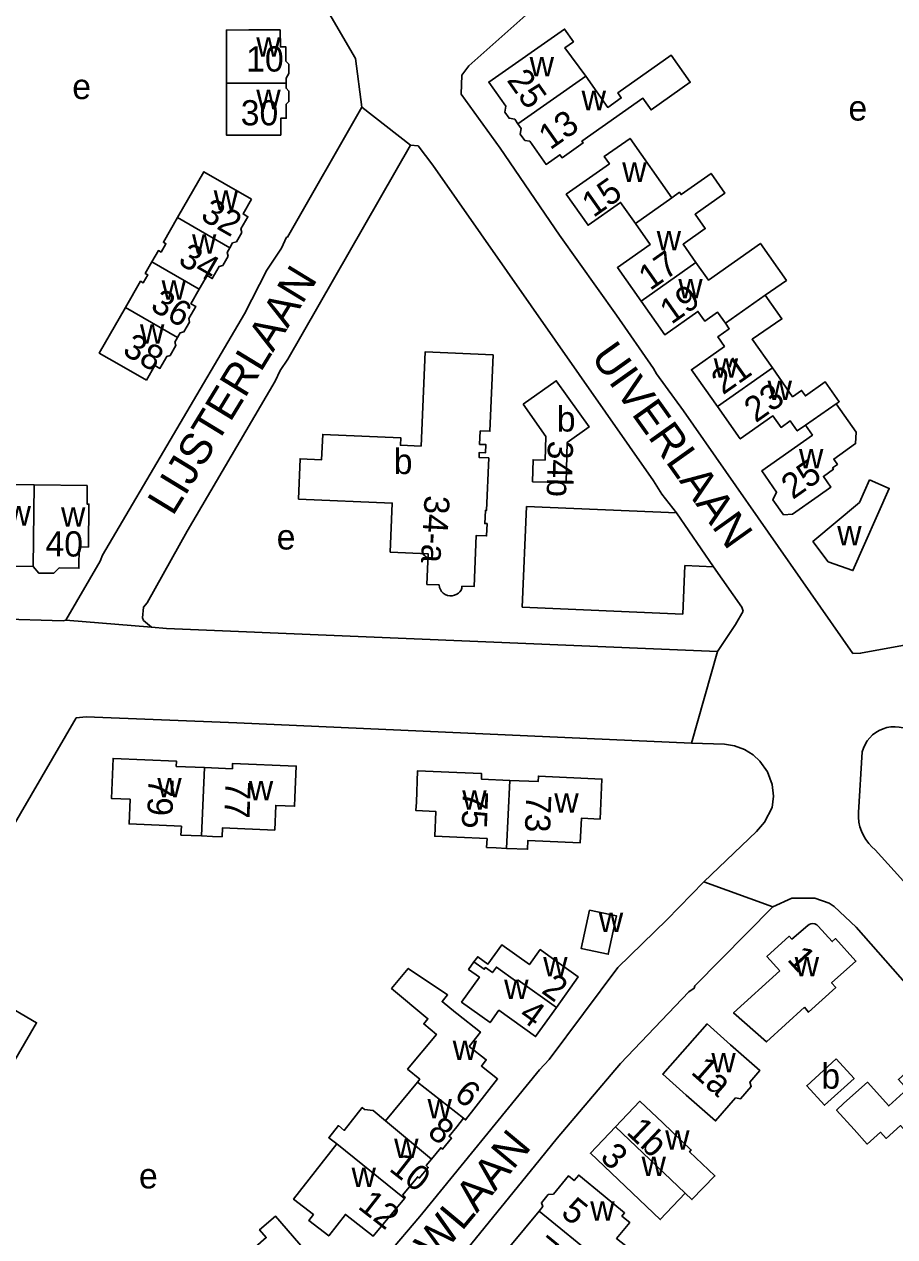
# Model space of a CAD drawing. Extents: x 161775 to 163181, y 382878 to 383925.
# Drawn here: x 162431.4 to 162569.5, y 383562.8 to 383755.2 of the extents above; entities that cross this region are included whole.
import ezdxf

# ---------------------------------------------------------------- set-up
doc = ezdxf.new("R2010")
doc.units = 0
for name, color, linetype in [('BLT_Basislijn', 7, 'Continuous'), ('BLT_Bebouwing', 7, 'Continuous'), ('BLT_Centroide', 7, 'Continuous'), ('BLT_Huisnummer', 7, 'Continuous'), ('BLT_Huisnummer_ tussenligend', 7, 'Continuous'), ('BLT_Huisnummer_reeks', 7, 'Continuous'), ('BLT_Onderverdeling_panden', 7, 'Continuous'), ('BLT_Straatnaam', 7, 'Continuous'), ('BLT_Vlakafsluiter', 7, 'Continuous')]:
    doc.layers.add(name, color=color, linetype=linetype)

msp = doc.modelspace()

# ---------------------------------------------------------------- linework, layer by layer
at = {"layer": 'BLT_Basislijn'}
for p, q in [((162471.79, 383770.6), (162483.91, 383749.78)), ((162483.91, 383749.78), (162484.96, 383742.04)), ((162484.96, 383742.04), (162473.14, 383721.44)), ((162473.19, 383702.07), (162492.67, 383736)), ((162492.67, 383736), (162493.88, 383735.92)), ((162493.88, 383735.92), (162496.2, 383732.84)), ((162496.2, 383732.84), (162531.21, 383682.78)), ((162472.98, 383721.44), (162472.2, 383719.67)), ((162473.14, 383721.44), (162472.98, 383721.44)), ((162472.2, 383719.67), (162469.88, 383716.2)), ((162469.88, 383716.2), (162466.31, 383709.26)), ((162466.31, 383709.26), (162443.82, 383670.95)), ((162471.98, 383700.26), (162473.19, 383702.07)), ((162471.18, 383698.57), (162471.98, 383700.26)), ((162457.22, 383674.75), (162471.18, 383698.57)), ((162531.21, 383682.78), (162532.49, 383680.64)), ((162532.49, 383680.64), (162534.85, 383677.66)), ((162511.07, 383678.7), (162510.38, 383662.73)), ((162511.07, 383678.7), (162534.85, 383677.66)), ((162534.85, 383677.66), (162540.71, 383669.12)), ((162450.87, 383663.42), (162457.22, 383674.75)), ((162443.82, 383670.95), (162443.46, 383670.03)), ((162443.46, 383670.03), (162437.98, 383660.67)), ((162535.85, 383661.62), (162536.19, 383669.32)), ((162540.71, 383669.12), (162536.19, 383669.32)), ((162540.71, 383669.12), (162545.19, 383662.72)), ((162450.3, 383662.72), (162450.87, 383663.42)), ((162450.17, 383661.04), (162450.3, 383662.72)), ((162510.38, 383662.73), (162535.85, 383661.62)), ((162545.41, 383662.09), (162544.22, 383659.95)), ((162545.19, 383662.72), (162545.41, 383662.09)), ((162437.59, 383660.52), (162425, 383660.96)), ((162437.98, 383660.67), (162437.59, 383660.52)), ((162450.33, 383660.62), (162450.17, 383661.04)), ((162451.57, 383659.53), (162450.33, 383660.62)), ((162453.94, 383659.34), (162451.57, 383659.53)), ((162541.37, 383655.69), (162453.94, 383659.34)), ((162544.22, 383659.95), (162541.37, 383655.69)), ((162412.37, 383598.34), (162439.64, 383645.18)), ((162439.64, 383645.18), (162441.21, 383645.29)), ((162441.21, 383645.29), (162465.12, 383644.39)), ((162465.12, 383644.39), (162537.22, 383641.15)), ((162537.22, 383641.15), (162542.43, 383640.97)), ((162564.3, 383639.76), (162563.69, 383630.15)), ((162548.8, 383628.62), (162547.54, 383627.14)), ((162547.54, 383627.14), (162539.2, 383619.13)), ((162566.35, 383624.21), (162577.05, 383612.32)), ((162539.2, 383619.13), (162533.33, 383613.11)), ((162533.33, 383613.11), (162525.53, 383605.54)), ((162525.53, 383605.54), (162514.66, 383590.97)), ((162514.66, 383590.97), (162513.14, 383589.33)), ((162513.14, 383589.33), (162494.16, 383566.07)), ((162494.16, 383566.07), (162488.99, 383560.01))]:
    msp.add_line(p, q, dxfattribs=at)
for points in [[(162581.31, 383759.17), (162559.03, 383792.81), (162557.89, 383792.62), (162542.81, 383782.75), (162531.95, 383775.94), (162528.54, 383772.6), (162528.54, 383772.35), (162501.9, 383748.57), (162500.78, 383747.14), (162500.69, 383744.11), (162506.86, 383735.52), (162516.26, 383721.74), (162525.33, 383709.05), (162531.21, 383700.6), (162531.65, 383699.73), (162535.97, 383693.84), (162562.82, 383655.34), (162564.03, 383655.39), (162577.08, 383657.78)], [(162570.77, 383643.55), (162570.14, 383643.68), (162569.5, 383643.74), (162568.86, 383643.71), (162568.22, 383643.61), (162567.6, 383643.43), (162567.01, 383643.17), (162566.45, 383642.85), (162565.94, 383642.45), (162565.48, 383642), (162565.08, 383641.49), (162564.75, 383640.94), (162564.48, 383640.35), (162564.3, 383639.76)], [(162542.43, 383640.97), (162544.05, 383640.71), (162545.65, 383640.13), (162547, 383639.28), (162548.07, 383638.26), (162549.3, 383636.58), (162550.01, 383634.57), (162550.21, 383632.74), (162549.99, 383630.95), (162548.8, 383628.62)], [(162563.69, 383630.15), (162563.69, 383629.39), (162563.78, 383628.63), (162563.94, 383627.89), (162564.18, 383627.18), (162564.49, 383626.49), (162564.87, 383625.83), (162565.33, 383625.22), (162565.84, 383624.67), (162566.35, 383624.21)], [(162550.13, 383615.17), (162537.75, 383602.64), (162537.62, 383602.25), (162536.8, 383601.68), (162525.96, 383590.3), (162515.92, 383578.47), (162512.31, 383574.02)], [(162571.49, 383602.7), (162563.33, 383611.96), (162559.83, 383615.2), (162559.03, 383615.74), (162556.77, 383616.56), (162553.14, 383616.56), (162550.13, 383615.17)], [(162512.31, 383574.02), (162490.5, 383547.14), (162490.5, 383546.29), (162493.91, 383542.53), (162494, 383541.83), (162480.94, 383530.56)]]:
    msp.add_lwpolyline(points, dxfattribs=at)
at = {"layer": 'BLT_Bebouwing'}
for p, q in [((162424.35, 383682.19), (162432.96, 383682.11)), ((162432.96, 383682.11), (162441.4, 383682.02)), ((162432.83, 383669.15), (162424.22, 383669.24)), ((162513.05, 383566.89), (162508.42, 383561.3))]:
    msp.add_line(p, q, dxfattribs=at)
for points in [[(162463.46, 383745.85), (162463.47, 383750), (162463.46, 383754.28), (162467.01, 383754.29), (162472.01, 383754.31)], [(162472.01, 383754.31), (162472.02, 383751.6), (162472.9, 383751.61), (162472.9, 383750), (162472.9, 383749.31), (162473.36, 383748.85), (162473.36, 383747.38), (162472.93, 383746.64), (162472.93, 383745.84)], [(162520.44, 383746.96), (162517.12, 383751.43), (162518.5, 383752.41), (162517.09, 383754.43), (162505.06, 383746.02), (162507.77, 383742.18), (162507.61, 383741.27), (162508.3, 383740.28), (162509.18, 383740.13), (162509.7, 383739.39)], [(162509.7, 383739.39), (162510.22, 383738.65), (162510.07, 383737.78), (162510.79, 383736.76), (162511.58, 383736.63), (162514.16, 383732.96), (162516.36, 383734.5), (162516.7, 383734.02), (162520.03, 383736.37), (162519.85, 383736.64), (162529.51, 383743.46), (162530.82, 383741.61), (162537.03, 383745.99), (162534, 383750.28), (162525.52, 383744.3), (162526.08, 383743.5), (162523.94, 383741.99), (162520.44, 383746.96)], [(162463.46, 383745.85), (162463.46, 383737.6), (162467.07, 383737.59), (162472.07, 383737.59)], [(162472.07, 383737.59), (162472.07, 383740.29), (162472.94, 383740.29), (162472.94, 383742.49), (162473.37, 383742.92), (162473.37, 383744.6), (162472.93, 383745.04), (162472.93, 383745.84)], [(162534.11, 383727.67), (162527.47, 383737.09), (162523.39, 383734.22), (162524.21, 383733.06), (162517.36, 383728.23), (162520.83, 383723.3), (162525.97, 383726.93), (162528.32, 383723.6)], [(162467.46, 383727.44), (162463.12, 383729.93), (162459.89, 383731.79), (162455.7, 383724.51)], [(162534.11, 383727.67), (162535.31, 383728.53), (162535.57, 383728.17), (162540.33, 383731.52), (162542.53, 383728.4), (162537.79, 383725.05), (162539.39, 383722.78), (162535.88, 383720.3), (162537.93, 383717.39)], [(162464.01, 383719.73), (162464.45, 383720.49), (162465.05, 383720.65), (162465.91, 383722.14), (162465.75, 383722.72), (162466.88, 383724.66), (162466.11, 383725.1), (162467.46, 383727.44)], [(162455.7, 383724.51), (162453.46, 383720.61), (162453.87, 383720.37), (162453.1, 383719.04), (162452.67, 383719.29), (162451.62, 383717.48)], [(162528.32, 383723.6), (162530.67, 383720.26), (162525.47, 383716.59), (162529.23, 383711.26)], [(162459.16, 383713.15), (162460.4, 383715.31), (162461.2, 383714.85), (162462.29, 383716.74), (162462.88, 383716.9), (162463.73, 383718.39), (162463.58, 383718.97), (162464.01, 383719.73)], [(162548.91, 383712.19), (162552.28, 383714.56), (162548.15, 383720.42), (162539.9, 383714.6), (162537.93, 383717.39)], [(162451.62, 383717.48), (162450.58, 383715.67), (162450.99, 383715.44), (162450.26, 383714.17), (162449.84, 383714.41), (162447.45, 383710.26)], [(162455.72, 383705.5), (162456.14, 383706.23), (162456.73, 383706.39), (162457.63, 383707.95), (162457.48, 383708.49), (162458.6, 383710.43), (162457.84, 383710.86), (162459.16, 383713.15)], [(162529.23, 383711.26), (162532.99, 383705.92), (162538.25, 383709.63), (162539.34, 383708.08), (162541.36, 383709.51), (162542.6, 383707.75)], [(162550.05, 383700.66), (162546.83, 383705.21), (162551.55, 383708.44), (162548.91, 383712.19)], [(162450.78, 383698.71), (162446.44, 383701.21), (162443.29, 383703.03), (162447.45, 383710.26)], [(162542.6, 383707.75), (162543.2, 383706.89), (162541.38, 383705.6), (162542.45, 383704.07), (162537.22, 383700.39), (162541.35, 383694.53)], [(162455.72, 383705.5), (162455.3, 383704.77), (162455.45, 383704.23), (162454.52, 383702.63), (162453.99, 383702.48), (162452.9, 383700.59), (162452.12, 383701.04), (162450.78, 383698.71)], [(162489.43, 383671.42), (162489.77, 383679.23), (162474.91, 383679.87), (162475.13, 383686.26), (162478.56, 383686.11), (162478.73, 383690.12), (162491.1, 383689.59), (162491.05, 383688.41), (162494.33, 383688.26), (162494.97, 383703.22), (162505.77, 383702.75)], [(162505.77, 383702.75), (162505.24, 383690.61), (162503.71, 383690.68), (162503.62, 383688.54), (162504.62, 383688.5), (162504.57, 383687.22), (162503.57, 383687.26), (162503.53, 383686.48), (162505.07, 383686.42)], [(162560.18, 383694.97), (162560.65, 383695.3), (162558.43, 383698.46), (162555.28, 383696.24), (162554.67, 383697.1), (162553.26, 383696.1), (162550.05, 383700.66)], [(162510.51, 383694.91), (162514.13, 383689.81), (162514, 383686.06), (162512.1, 383686.1), (162512.01, 383682.61), (162517.35, 383682.55), (162517.52, 383688.85), (162520.97, 383691.31), (162515.77, 383698.64), (162510.51, 383694.91)], [(162541.35, 383694.53), (162544.96, 383689.41), (162550.13, 383693.06), (162551.42, 383691.23), (162552.88, 383692.26), (162554, 383690.67), (162555.3, 383691.57)], [(162560.18, 383694.97), (162563.35, 383690.48), (162563.25, 383688.66), (162559.77, 383686.2), (162560.37, 383685.35), (162559.59, 383684.8), (162559.74, 383684.6), (162558.14, 383683.46), (162559.33, 383681.77), (162557.31, 383680.35), (162553.22, 383677.47), (162551.82, 383677.34), (162550.14, 383679.73), (162550.72, 383680.98), (162548.35, 383684.34), (162556.4, 383690.01), (162555.3, 383691.57)], [(162500.82, 383666.06), (162502.74, 383665.98), (162503.09, 383674.09), (162504.71, 383674.02), (162504.79, 383675.97), (162504.44, 383675.98), (162504.53, 383678.06), (162504.7, 383678.05), (162505.07, 383686.42)], [(162441.4, 383682.02), (162441.37, 383679.08), (162441.65, 383679.08), (162441.58, 383672.25), (162440.1, 383672.26), (162440.07, 383668.9), (162436.94, 383668.93), (162436.09, 383668.1)], [(162489.43, 383671.42), (162495.46, 383671.16), (162495.25, 383666.32), (162497.2, 383666.24)], [(162436.09, 383668.1), (162433.7, 383668.12), (162432.83, 383669.15)], [(162497.2, 383666.24), (162497.25, 383665.86), (162497.39, 383665.5), (162497.59, 383665.18), (162497.86, 383664.91), (162498.17, 383664.7), (162498.53, 383664.56), (162498.9, 383664.49), (162499.28, 383664.51), (162499.65, 383664.61), (162499.99, 383664.78), (162500, 383664.78)], [(162500.82, 383666.06), (162500.78, 383665.74), (162500.67, 383665.43), (162500.49, 383665.15), (162500.25, 383664.93), (162500, 383664.78)], [(162459.96, 383637.26), (162455.51, 383637.45), (162455.54, 383638.29), (162445.49, 383638.71), (162445.23, 383632.36), (162448.19, 383632.23), (162448.02, 383628.32), (162456.31, 383627.97), (162456.25, 383626.56), (162459.5, 383626.43)], [(162459.5, 383626.43), (162461.24, 383626.35), (162462.76, 383626.29), (162462.82, 383627.69), (162471.12, 383627.34), (162471.28, 383631.26), (162474.26, 383631.14), (162474.32, 383632.5), (162474.53, 383637.49), (162464.44, 383637.92), (162464.4, 383637.08), (162459.96, 383637.26)], [(162507.9, 383624.45), (162506.23, 383624.52), (162504.72, 383624.59), (162504.79, 383626), (162500, 383626.22), (162496.5, 383626.38), (162496.68, 383630.28), (162493.52, 383630.43), (162493.58, 383631.76), (162493.79, 383636.75), (162500, 383636.49), (162503.93, 383636.3), (162503.89, 383635.45), (162508.39, 383635.24)], [(162508.39, 383635.24), (162512.9, 383635.04), (162512.94, 383635.91), (162523, 383635.45), (162522.71, 383629.1), (162519.76, 383629.23), (162519.58, 383625.33), (162511.29, 383625.7), (162511.23, 383624.3), (162507.9, 383624.45)], [(162521.02, 383614.66), (162525.31, 383613.76), (162524.02, 383607.66), (162519.73, 383608.56), (162521.02, 383614.66)], [(162551.24, 383605.04), (162549.19, 383607.29), (162552.73, 383610.51), (162553.15, 383610.05), (162555.65, 383612.23)], [(162557.33, 383612.13), (162559.54, 383609.65), (162560.07, 383610.13), (162563.29, 383606.57), (162559.43, 383603.09), (162560.1, 383602.35), (162555.8, 383598.46), (162555.12, 383599.23)], [(162557.33, 383612.13), (162557.09, 383612.33), (162556.8, 383612.45), (162556.48, 383612.51), (162556.17, 383612.48), (162555.87, 383612.37), (162555.65, 383612.23)], [(162502.72, 383606.44), (162503.31, 383607.25), (162504.94, 383606.08), (162507.13, 383609.14), (162511.51, 383606.01), (162513.22, 383608.39), (162515.2, 383606.97), (162519.27, 383604.06), (162515.79, 383599.2)], [(162493.75, 383587.36), (162494.13, 383587.83), (162492.2, 383589.43), (162496.76, 383594.93), (162494.75, 383596.61), (162495.43, 383597.43), (162489.66, 383602.22), (162492.31, 383605.41), (162498.54, 383601.19), (162497.67, 383600.13), (162499.8, 383598.42), (162500, 383598.25), (162503.74, 383595.3), (162501.96, 383593.04), (162504.66, 383590.9), (162503.89, 383589.92), (162506.47, 383587.87), (162501.4, 383581.38), (162501.06, 383581.65)], [(162502.72, 383606.44), (162501.86, 383605.24), (162503.59, 383604.01), (162500.75, 383600.05), (162505.27, 383596.8), (162506.68, 383598.77), (162512.49, 383594.6), (162515.79, 383599.2)], [(162551.24, 383605.04), (162543.9, 383598.34), (162549.09, 383593.75), (162555.12, 383599.23)], [(162419.03, 383596.27), (162419.5, 383597.09), (162419.23, 383598.12), (162420.01, 383599.47), (162421.01, 383599.74), (162421.52, 383600.63), (162421.91, 383600.4), (162423.19, 383602.63), (162427.52, 383600.13), (162433.34, 383596.78), (162429.54, 383590.2), (162428.32, 383590.91)], [(162543.43, 383593.28), (162548.08, 383589.19), (162546.47, 383587.38), (162546.71, 383586.67), (162544.97, 383584.7), (162544.22, 383584.85), (162541.03, 383581.22), (162536.4, 383585.3), (162532.65, 383588.6), (162539.68, 383596.59), (162543.43, 383593.28)], [(162572.93, 383577.64), (162578.49, 383582.65), (162582.2, 383586), (162577.17, 383591.58), (162575.84, 383590.38), (162574.54, 383591.83), (162570.04, 383587.78), (162571.43, 383586.25), (162568.5, 383583.6), (162565.12, 383587.35), (162561.4, 383584), (162560.22, 383582.94), (162563.02, 383579.83), (162565.09, 383577.54), (162567.17, 383579.42), (162568.08, 383578.42), (162570.37, 383580.48), (162572.93, 383577.64)], [(162488.67, 383581.24), (162493.75, 383587.36)], [(162536.24, 383569.73), (162537.3, 383568.72), (162540.94, 383572.49), (162536.91, 383576.32), (162537.18, 383576.6), (162537.18, 383576.59), (162532.65, 383580.9), (162529.02, 383584.34), (162525.15, 383580.27)], [(162488.67, 383581.24), (162486.75, 383582.84), (162485.38, 383583), (162484.99, 383583.32), (162482.14, 383579.71), (162481.22, 383580.48), (162479.69, 383578.55), (162480.98, 383577.55)], [(162496.01, 383575.15), (162497.44, 383576.95), (162497.72, 383576.71), (162499.16, 383578.45), (162498.77, 383578.77), (162500, 383580.25), (162501.06, 383581.65)], [(162525.15, 383580.27), (162521.18, 383576.09), (162532.27, 383565.56), (162536.24, 383569.73)], [(162480.98, 383577.55), (162474.12, 383568.78), (162477.25, 383566.35), (162476.52, 383565.42), (162479.68, 383562.96), (162482.33, 383566.37), (162486.74, 383562.94), (162491.69, 383568.92)], [(162496.01, 383575.15), (162495.15, 383574.11), (162495.26, 383574.02)], [(162495.26, 383574.02), (162495.47, 383573.84), (162494.05, 383572.13), (162493.8, 383572.34), (162491.4, 383569.44)], [(162522.51, 383559.16), (162523.98, 383557.96), (162526.8, 383561.37), (162525.34, 383562.58), (162527.42, 383565.08), (162526.19, 383566.1), (162526.61, 383566.6), (162523.2, 383569.43), (162519.35, 383572.62), (162518.61, 383571.73), (162517.71, 383572.47), (162515.33, 383569.6), (162514.49, 383569.52), (162513.42, 383568.23), (162513.65, 383567.61), (162513.05, 383566.89)], [(162491.4, 383569.44), (162491.83, 383569.09), (162491.69, 383568.92)], [(162466.69, 383560.04), (162469.79, 383562.7), (162468.72, 383563.93), (162471.24, 383566.11), (162476.95, 383559.49), (162480.21, 383555.7), (162477.43, 383553.3), (162477.74, 383552.93), (162475.28, 383550.82), (162474.95, 383551.2), (162474.47, 383550.79), (162474.11, 383551.22)]]:
    msp.add_lwpolyline(points, dxfattribs=at)
for points in [[(162565.46, 383682.94), (162568.59, 383681.55), (162562.81, 383668.51), (162558.91, 383669.93), (162556.48, 383673.11), (162563.86, 383679.31)], [(162560.17, 383591.04), (162563, 383587.93), (162558.34, 383583.69), (162555.51, 383586.79)]]:
    msp.add_lwpolyline(points, close=True, dxfattribs=at)
at = {"layer": 'BLT_Onderverdeling_panden'}
for p, q in [((162472.93, 383745.84), (162463.46, 383745.85)), ((162520.44, 383746.96), (162509.7, 383739.39)), ((162528.32, 383723.6), (162534.11, 383727.67)), ((162464.01, 383719.73), (162455.7, 383724.51)), ((162451.62, 383717.48), (162459.16, 383713.15)), ((162529.23, 383711.26), (162537.93, 383717.39)), ((162542.6, 383707.75), (162548.91, 383712.19)), ((162455.72, 383705.5), (162447.45, 383710.26)), ((162550.05, 383700.66), (162541.35, 383694.53)), ((162555.3, 383691.57), (162560.18, 383694.97)), ((162432.96, 383682.11), (162432.83, 383669.15)), ((162459.96, 383637.26), (162459.5, 383626.43)), ((162508.39, 383635.24), (162507.9, 383624.45)), ((162501.06, 383581.65), (162493.75, 383587.36)), ((162488.67, 383581.24), (162496.01, 383575.15)), ((162525.15, 383580.27), (162531.72, 383574.02)), ((162491.69, 383568.92), (162480.98, 383577.55)), ((162531.72, 383574.02), (162536.24, 383569.73)), ((162522.51, 383559.16), (162513.05, 383566.89))]:
    msp.add_line(p, q, dxfattribs=at)
msp.add_lwpolyline([(162515.79, 383599.2), (162509.71, 383603.55), (162509.52, 383603.29), (162506.28, 383605.61), (162505.65, 383604.73), (162504.54, 383605.53), (162504.36, 383605.27), (162502.72, 383606.44)], dxfattribs=at)
at = {"layer": 'BLT_Vlakafsluiter'}
for p, q in [((162484.96, 383742.04), (162492.67, 383736)), ((162437.98, 383660.67), (162451.57, 383659.53)), ((162537.22, 383641.15), (162541.37, 383655.69)), ((162550.13, 383615.17), (162539.2, 383619.13))]:
    msp.add_line(p, q, dxfattribs=at)

# ---------------------------------------------------------------- texts
at = {"layer": 'BLT_Centroide'}
for s, p in [('w', (162468.19, 383750.06)), ('w', (162511.55, 383746.91)), ('e', (162439.01, 383743.32)), ('w', (162468.2, 383741.72)), ('w', (162519.79, 383741.56)), ('e', (162562.11, 383739.91)), ('w', (162526.24, 383730.19)), ('w', (162461.45, 383725.75)), ('w', (162458, 383718.81)), ('w', (162531.7, 383719.33)), ('w', (162453.18, 383711.5)), ('w', (162535.13, 383711.73)), ('w', (162449.75, 383704.5)), ('w', (162540.75, 383699.12)), ('w', (162549.29, 383695.56)), ('b', (162515.86, 383690.58)), ('b', (162490, 383683.84)), ('w', (162554.27, 383684.72)), ('w', (162428.59, 383675.67)), ('w', (162437.23, 383675.5)), ('e', (162471.43, 383671.86)), ('w', (162560.33, 383672.52)), ('w', (162452.5, 383632.56)), ('w', (162467.02, 383632.09)), ('w', (162500.86, 383630.59)), ('w', (162515.46, 383630.09)), ('w', (162522.52, 383611.16)), ('w', (162513.7, 383604.16)), ('w', (162553.59, 383604.14)), ('w', (162507.51, 383600.53)), ('w', (162499.34, 383590.89)), ('w', (162540.37, 383588.91)), ('b', (162557.81, 383586.32)), ('w', (162495.35, 383581.62)), ('w', (162533.05, 383576.66)), ('w', (162490.06, 383575.31)), ('w', (162529.3, 383572.47)), ('e', (162449.59, 383570.5)), ('w', (162483.31, 383570.73)), ('w', (162521.16, 383565.38))]:
    msp.add_text(s, height=4, dxfattribs=at).set_placement(p)
at = {"layer": 'BLT_Huisnummer'}
for s, rotation, p in [('10', 359.9637, (162466.59, 383747.69)), ('25', 305.1825, (162507.83, 383746.31)), ('30', 359.9885, (162465.73, 383739.15)), ('13', 35.1789, (162514.81, 383735.16)), ('15', 35.1839, (162521.66, 383724.43)), ('32', 330.0787, (162459.16, 383724.33)), ('19', 35.1889, (162534.03, 383707.48)), ('38', 330.0661, (162446.79, 383702.94)), ('23', 35.1785, (162547.4, 383691.87)), ('34b', 268.647, (162514.46, 383689.16)), ('25', 35.1807, (162553.28, 383679.7)), ('40', 359.4133, (162434.74, 383670.79)), ('79', 267.9836, (162451.11, 383635.61)), ('77', 267.9836, (162463.33, 383635.22)), ('75', 267.9836, (162500.98, 383633.6)), ('73', 267.9836, (162511, 383633)), ('1', 312.4436, (162552.26, 383606.75)), ('2', 324.39, (162513.25, 383601.63)), ('4', 324.39, (162509.65, 383597.54)), ('1a', 318.6405, (162536.96, 383588.8)), ('6', 322.0162, (162499.36, 383584.94)), ('1b', 316.4713, (162526.73, 383579.28)), ('3', 316.475, (162522.56, 383575.24)), ('12', 322.0162, (162484.14, 383567.43)), ('5', 320.7437, (162516.33, 383566.33))]:
    msp.add_text(s, height=4, rotation=rotation, dxfattribs=at).set_placement(p)
at = {"layer": 'BLT_Huisnummer_ tussenligend'}
for s, rotation, p in [('34', 330.0787, (162455.61, 383717.26)), ('17', 35.1839, (162530.65, 383712.84)), ('36', 330.06, (162451.21, 383709.97)), ('21', 35.1889, (162542.21, 383696.31)), ('8', 322.0162, (162495.15, 383579.06)), ('10', 322.0162, (162489.09, 383573.41)), ('7', 320.7437, (162511.63, 383560.23))]:
    msp.add_text(s, height=4, rotation=rotation, dxfattribs=at).set_placement(p)
at = {"layer": 'BLT_Huisnummer_reeks'}
msp.add_text('34-a', height=4, rotation=266.8983, dxfattribs=at).set_placement((162494.9, 383680.53))
at = {"layer": 'BLT_Straatnaam'}
for s, height, rotation, p in [('LIJSTERLAAN', 4.9999, 58.5817, (162454.96, 383677.04)), ('UIVERLAAN', 5, 305.4682, (162521.15, 383702.45)), ('PAUWLAAN', 5, 50.1275, (162487.94, 383548.23))]:
    msp.add_text(s, height=height, rotation=rotation, dxfattribs=at).set_placement(p)

doc.saveas('drawing.dxf')
